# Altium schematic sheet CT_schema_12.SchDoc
size 519 x 434 mm
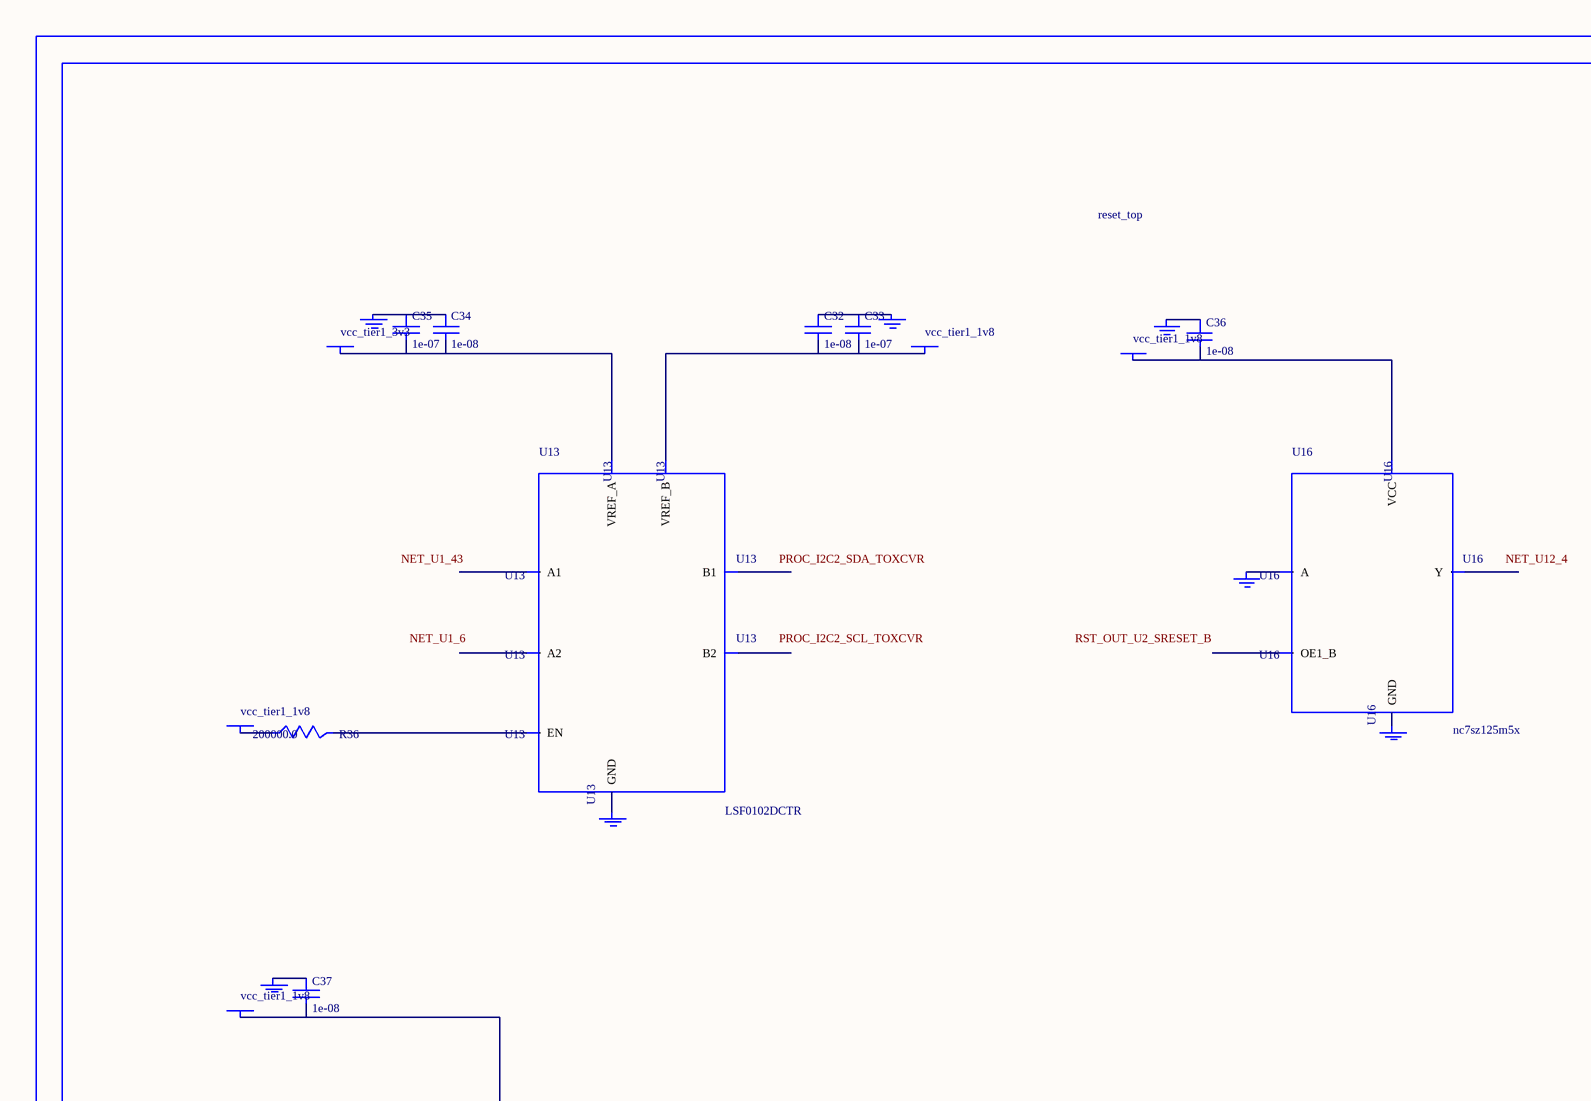
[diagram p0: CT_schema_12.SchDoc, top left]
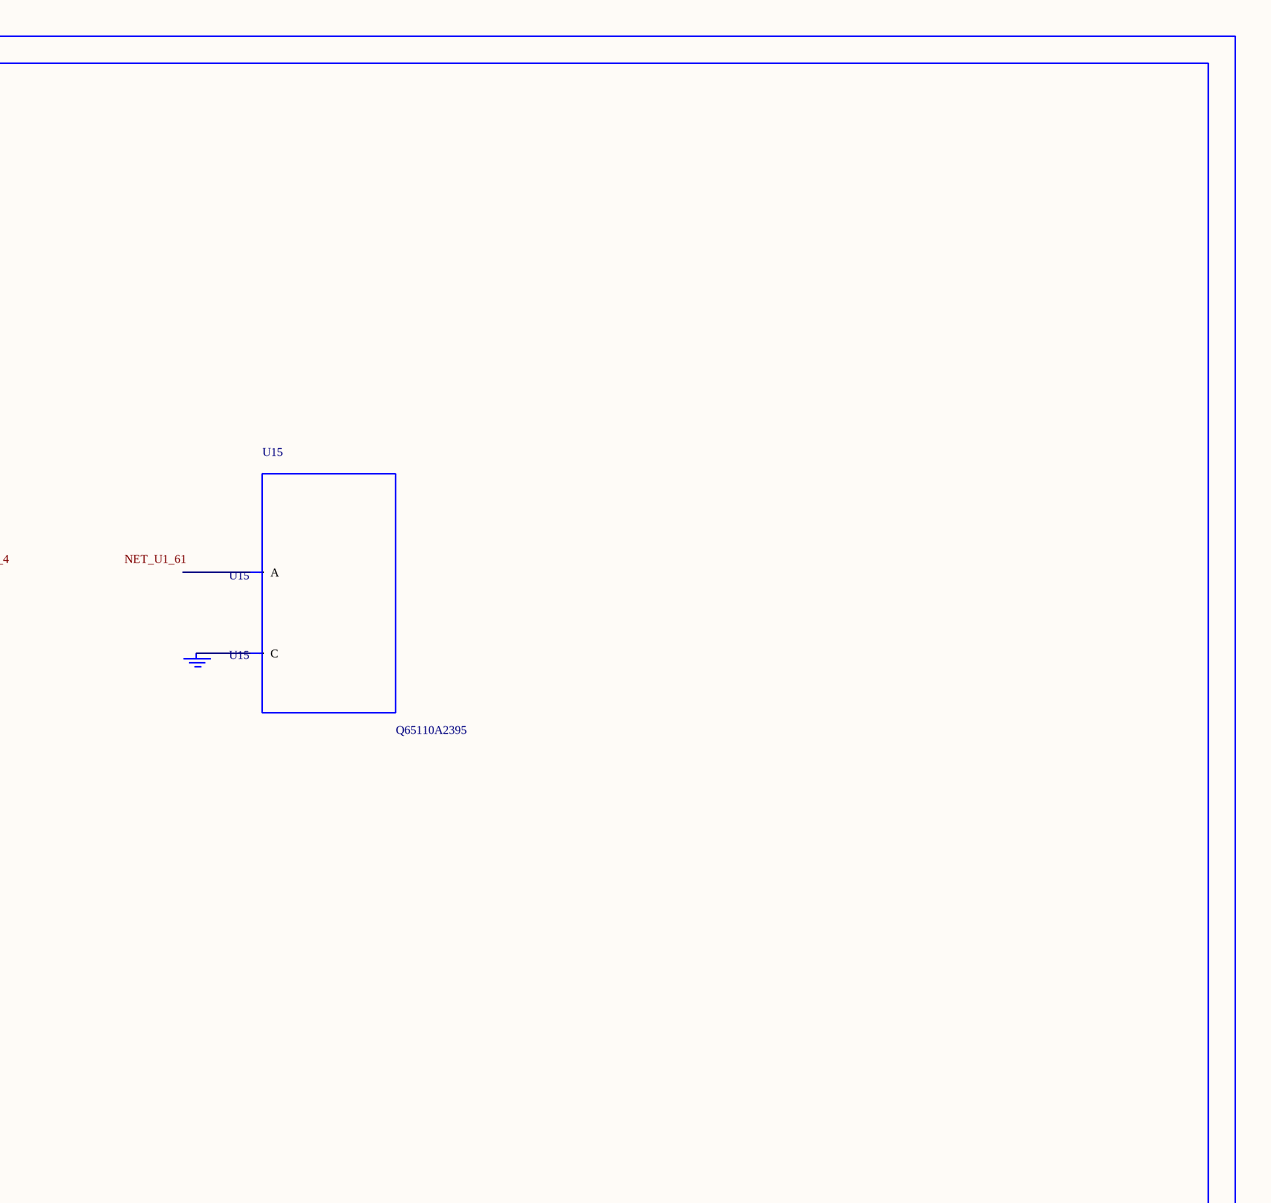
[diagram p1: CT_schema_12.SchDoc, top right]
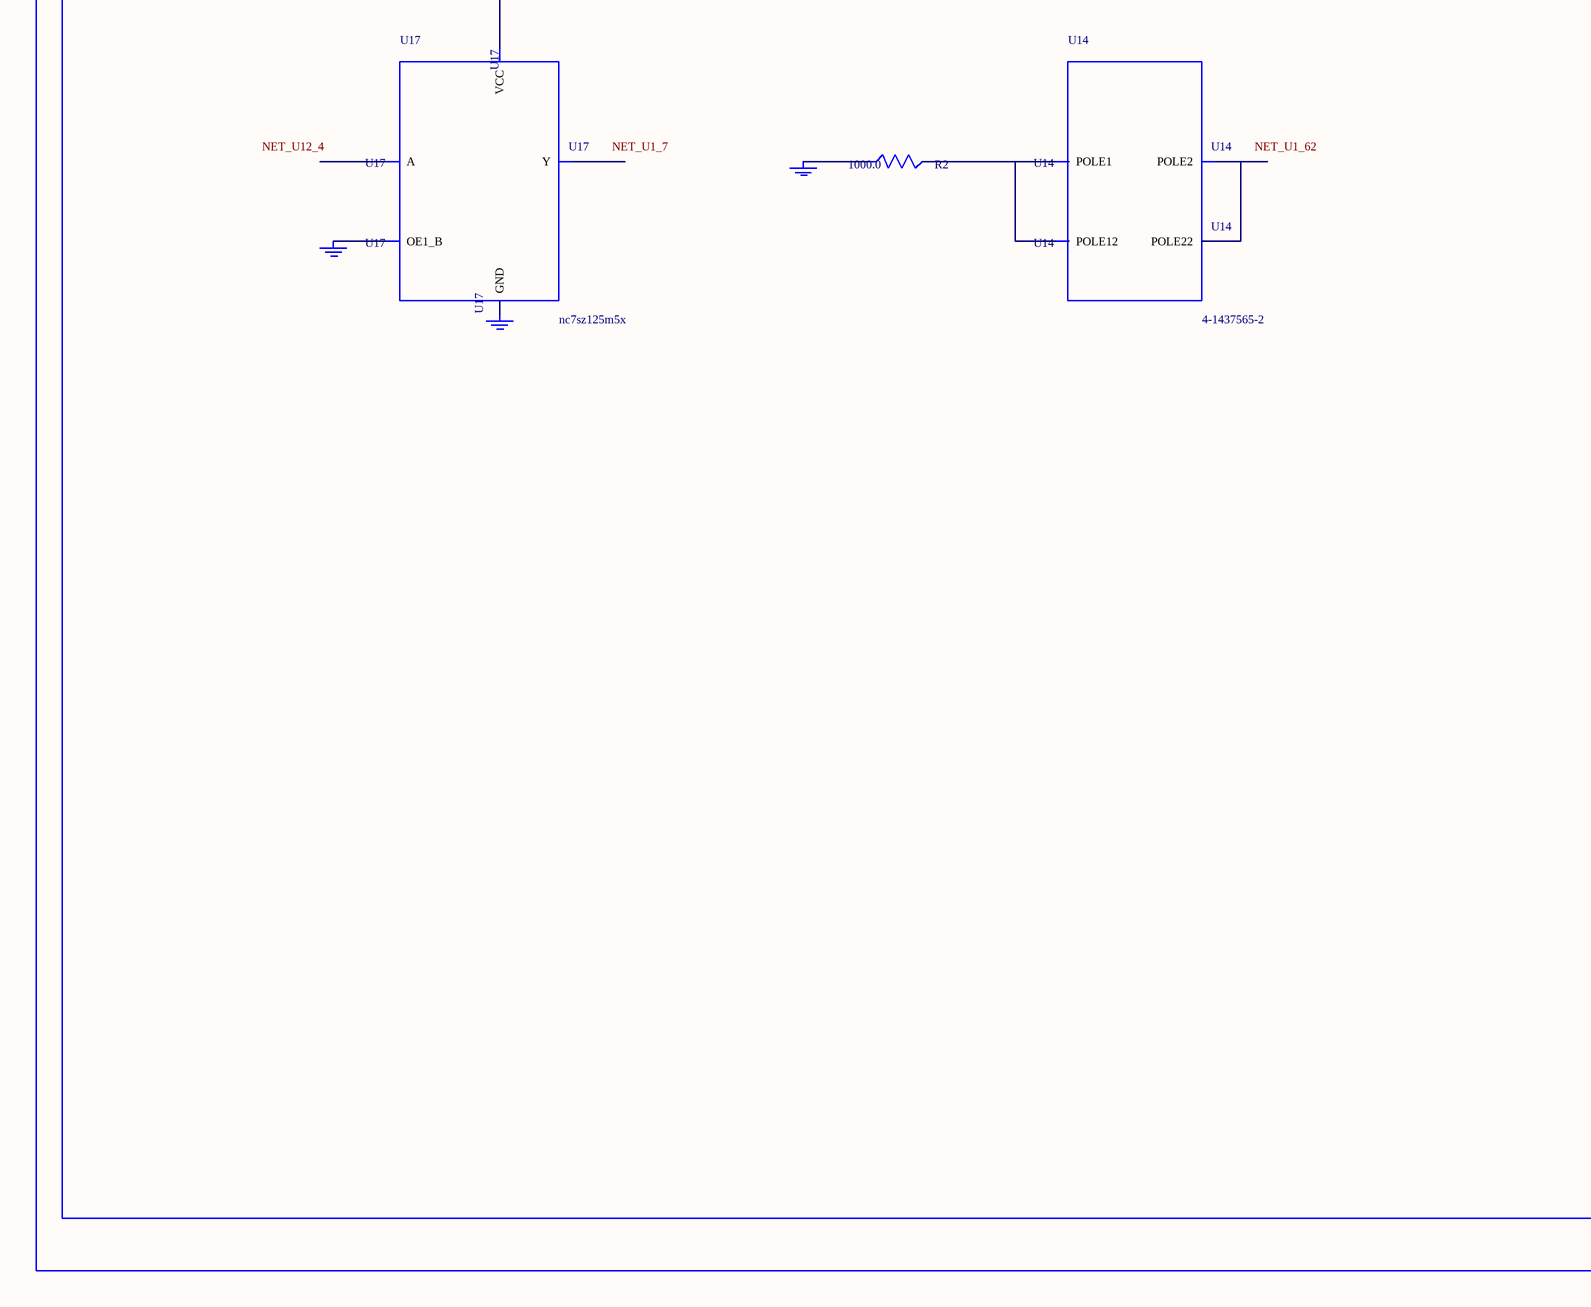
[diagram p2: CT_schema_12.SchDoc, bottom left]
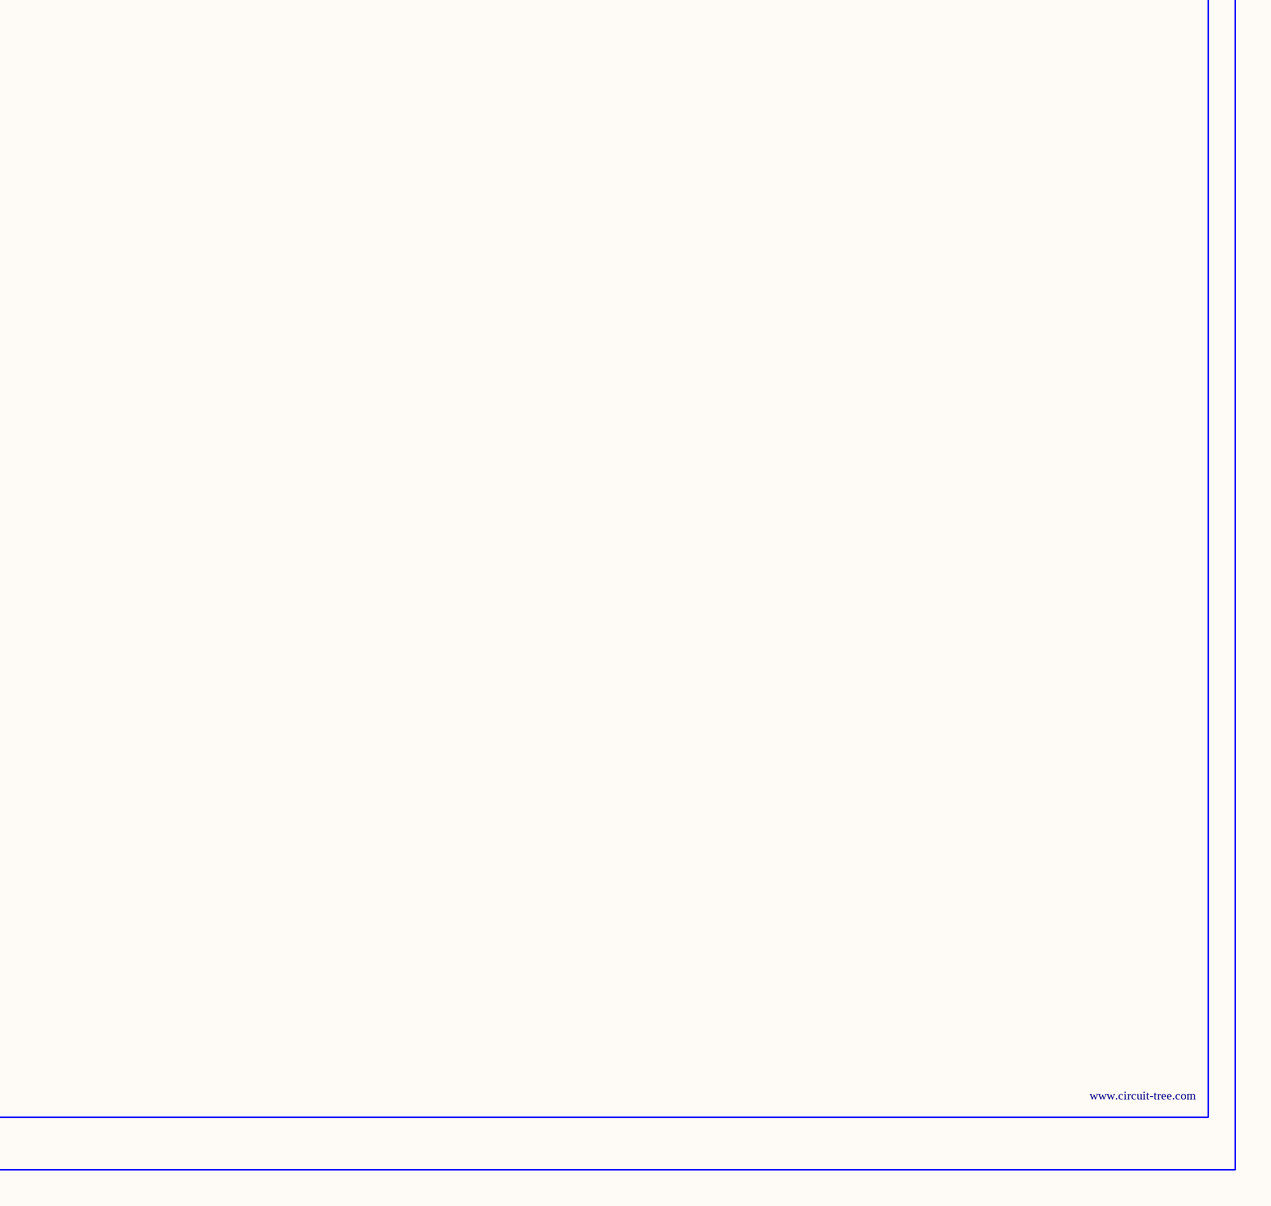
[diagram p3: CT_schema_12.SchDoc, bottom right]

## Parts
BORDER11  (no value)
C32  1e-08  [C0402]
C33  1e-07  [C0402]
C34  1e-08  [C0402]
C35  1e-07  [C0402]
C36  1e-08  [C0402]
C37  1e-08  [C0402]
GND_INSTANCE_11_0  (no value)
GND_INSTANCE_11_1  (no value)
GND_INSTANCE_11_2  (no value)
GND_INSTANCE_11_3  (no value)
GND_INSTANCE_11_4  (no value)
GND_INSTANCE_11_5  (no value)
GND_INSTANCE_11_6  (no value)
GND_INSTANCE_11_7  (no value)
GND_INSTANCE_11_8  (no value)
GND_INSTANCE_11_9  (no value)
GND_INSTANCE_11_10  (no value)
POWER_INSTANCE_11_0  vcc_tier1_3v3
POWER_INSTANCE_11_1  vcc_tier1_1v8
POWER_INSTANCE_11_2  vcc_tier1_1v8
POWER_INSTANCE_11_3  vcc_tier1_1v8
POWER_INSTANCE_11_4  vcc_tier1_1v8
R2  1000.0  [R0603]
R36  200000.0  [R0603]
U13  LSF0102DCTR  [DCU0008A_N]
U14  4-1437565-2  [SW_4-1437565-2]
U15  Q65110A2395  [LGM67K-G1J2-24-Z]
U16  nc7sz125m5x  [NC7SZ125M5X]
U17  nc7sz125m5x  [NC7SZ125M5X]

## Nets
NetC32_1: C32.1 C33.1 GND_INSTANCE_11_1.0(GND)
NetC32_2: C32.2 C33.2 POWER_INSTANCE_11_1.0(PWR) U13.7(VREF_B)
NetC34_1: C34.1 C35.1 GND_INSTANCE_11_0.0(GND)
NetC34_2: C34.2 C35.2 POWER_INSTANCE_11_0.0(PWR) U13.2(VREF_A)
NetC36_1: C36.1 GND_INSTANCE_11_5.0(GND)
NetC36_2: C36.2 POWER_INSTANCE_11_3.0(PWR) U16.5(VCC)
NetC37_1: C37.1 GND_INSTANCE_11_8.0(GND)
NetC37_2: C37.2 POWER_INSTANCE_11_4.0(PWR) U17.5(VCC)
NetGND_INSTANCE_11_2_0: GND_INSTANCE_11_2.0(GND) U13.1(GND)
NetGND_INSTANCE_11_3_0: GND_INSTANCE_11_3.0(GND) R2.1
NetGND_INSTANCE_11_4_0: GND_INSTANCE_11_4.0(GND) U15.C
NetGND_INSTANCE_11_6_0: GND_INSTANCE_11_6.0(GND) U16.2(A)
NetGND_INSTANCE_11_7_0: GND_INSTANCE_11_7.0(GND) U16.3(GND)
NetGND_INSTANCE_11_9_0: GND_INSTANCE_11_9.0(GND) U17.1(OE1_B)
NetGND_INSTANCE_11_10_0: GND_INSTANCE_11_10.0(GND) U17.3(GND)
NetPOWER_INSTANCE_11_2_0: POWER_INSTANCE_11_2.0(PWR) R36.1
NetR2_2: R2.2 U14.1(POLE1) U14.2(POLE12)
NetR36_2: R36.2 U13.8(EN)
NetU14_3: U14.3(POLE2) U14.4(POLE22)

Not connected (* = marked no-connect by the designer): U13 3(A1) 4(A2) 5(B2) 6(B1); U15 A; U16 1(OE1_B) 4(Y); U17 2(A) 4(Y)

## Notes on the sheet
- Labels drawn without touching a wire or pin: NET_U1_6, NET_U1_7, NET_U1_43, NET_U1_61, NET_U1_62, NET_U12_4, PROC_I2C2_SCL_TOXCVR, PROC_I2C2_SDA_TOXCVR, RST_OUT_U2_SRESET_B

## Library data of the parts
BORDER11 = BORDER_PAGE11
C32 C34 C36 C37 = C0402C103K3RAC
C33 C35 = C0402C104K3RACTU
GND_INSTANCE_11_0-GND_INSTANCE_11_10 = GND
POWER_INSTANCE_11_0-POWER_INSTANCE_11_4 = PWR
R2 = RC0603JR-071KL
R36 = RC0603JR-07200KL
